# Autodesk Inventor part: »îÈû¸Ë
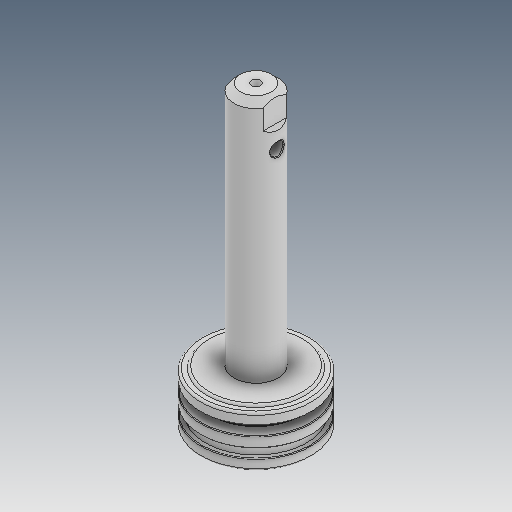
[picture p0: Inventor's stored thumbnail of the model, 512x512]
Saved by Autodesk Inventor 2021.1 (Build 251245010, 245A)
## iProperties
Created: 2013-04
Part Number: »îÈû¸Ë
Material: Ogólny
Document SubType Name: Modeling
Designer: user
Density: 1 g/cm^3
Appearance: Domyślna
Author: user
Revision Number: ÈÎºÎ
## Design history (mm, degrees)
feature "ÇÐ³ý-À­Éì1"
node "Bryła1"
